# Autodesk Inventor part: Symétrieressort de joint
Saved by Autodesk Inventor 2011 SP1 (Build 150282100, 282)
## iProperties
Created: 2010-12
Part Number: Symétrieressort de joint
Document SubType Name: Modeling
Designer: eric
Density: 1 g/cm^3
Author: eric
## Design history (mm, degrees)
feature "Base1"
node "Solide1"
node "Corps solides"
node "Corps surfaciques"
